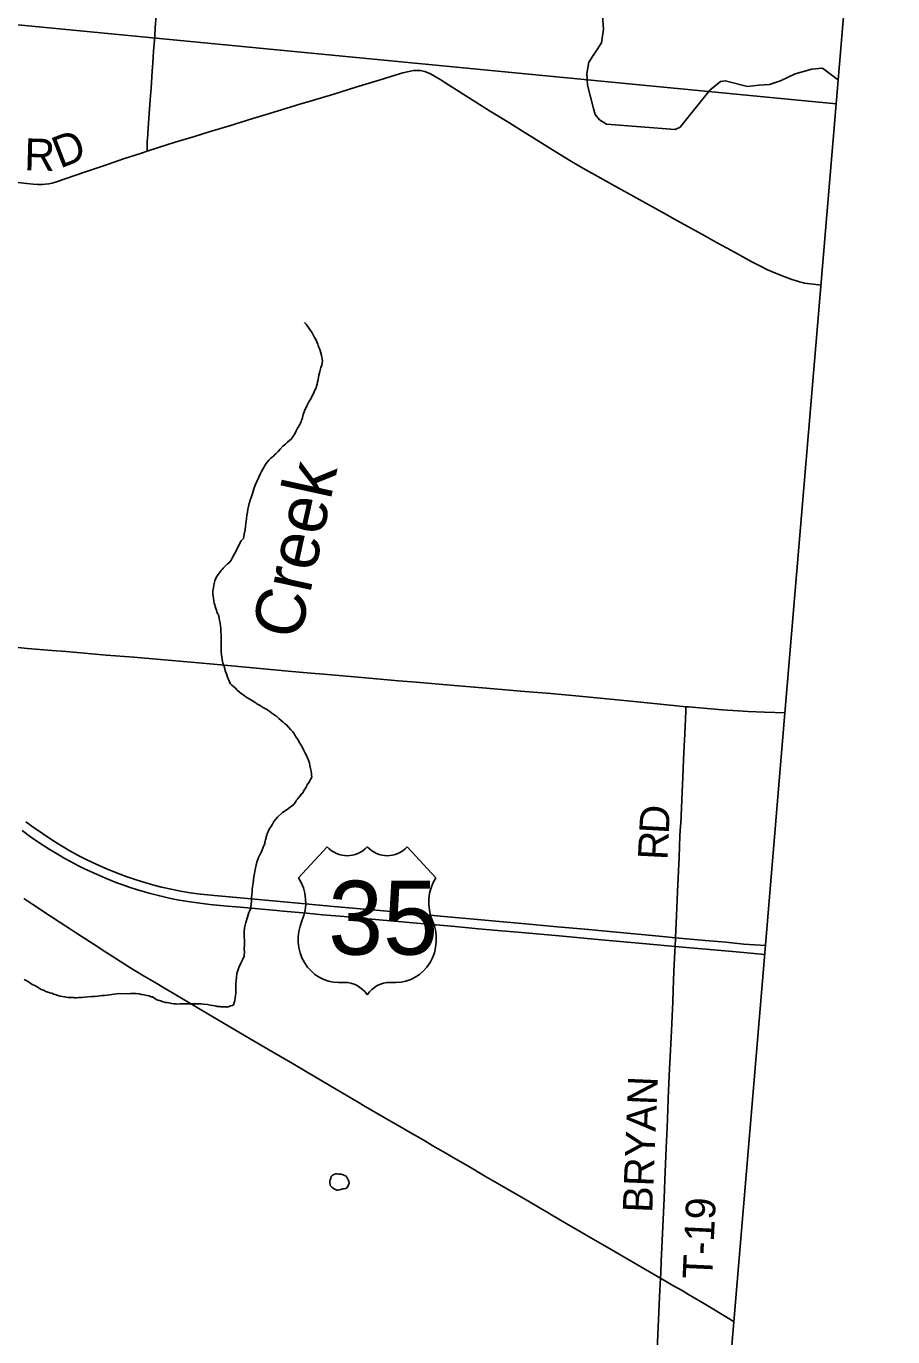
# Model space of a CAD drawing. Extents: x -13.9 to 69.1, y -25.2 to 26.1.
# Drawn here: x 6.483 to 7.963, y 16.353 to 18.591 of the extents above; entities that cross this region are included whole.
import ezdxf

# ---------------------------------------------------------------- set-up
doc = ezdxf.new("R2010")
doc.units = 0
for name, color, linetype in [('GM_X_County_Road', 7, 'Continuous'), ('GM_X_County_Road_Text', 7, 'Continuous'), ('GM_X_Minor_Lake', 7, 'Continuous'), ('GM_X_Minor_River', 7, 'Continuous'), ('GM_X_Minor_River_Text', 7, 'Continuous'), ('GM_X_State_Route', 7, 'Continuous'), ('GM_X_Township', 7, 'Continuous'), ('GM_X_Township_Road', 7, 'Continuous'), ('GM_X_Township_Road_Text', 7, 'Continuous'), ('GM_X_US_Location', 7, 'Continuous'), ('GM_X_US_Route', 7, 'Continuous'), ('GM_X_US_Shield', 7, 'Continuous')]:
    doc.layers.add(name, color=color, linetype=linetype)

msp = doc.modelspace()

# ---------------------------------------------------------------- linework, layer by layer
at = {"layer": 'GM_X_County_Road'}
for points in [[(6.6892, 18.378), (6.7087, 18.3844), (6.7375, 18.3932), (6.7705, 18.4032), (6.7954, 18.4109), (6.83, 18.4215), (6.8699, 18.4335), (6.8986, 18.4424), (6.9502, 18.4582), (6.9715, 18.4646), (7.0082, 18.4756), (7.046, 18.4871), (7.0854, 18.499), (7.113, 18.5076), (7.1258, 18.5115), (7.1339, 18.5136), (7.139, 18.5148), (7.1443, 18.5156), (7.1486, 18.5159), (7.1527, 18.5159), (7.1563, 18.5155), (7.1605, 18.5147), (7.1638, 18.5138), (7.1675, 18.5126), (7.1722, 18.5106), (7.1773, 18.508), (7.1831, 18.5045), (7.1908, 18.4997), (7.1979, 18.4952), (7.2509, 18.4618), (7.2742, 18.4471), (7.3068, 18.4269), (7.3302, 18.4123), (7.3499, 18.4002), (7.3772, 18.3832), (7.4011, 18.3682), (7.4141, 18.3604), (7.4335, 18.349), (7.4589, 18.3346), (7.4874, 18.3188), (7.5257, 18.2975), (7.5729, 18.2713), (7.5901, 18.2619), (7.6417, 18.2333), (7.6619, 18.2222), (7.6875, 18.2082), (7.7116, 18.1948), (7.7219, 18.1892), (7.7367, 18.1815), (7.7489, 18.1755), (7.7544, 18.1728), (7.7652, 18.1685), (7.7785, 18.1632), (7.7902, 18.1591), (7.7985, 18.1563), (7.8031, 18.155), (7.8078, 18.1539), (7.8119, 18.1528), (7.8169, 18.1518), (7.8408, 18.1492)], [(6.4236, 18.3298), (6.4841, 18.323), (6.4945, 18.3219), (6.5028, 18.3213), (6.5099, 18.3212), (6.5154, 18.3215), (6.5213, 18.3223), (6.5272, 18.3236), (6.5346, 18.3258), (6.5826, 18.3421), (6.6216, 18.3553), (6.649, 18.3647), (6.6797, 18.3748), (6.6892, 18.378)], [(6.4787, 17.1015), (6.4943, 17.0913), (6.5023, 17.0861), (6.5127, 17.0792), (6.5411, 17.0608), (6.5586, 17.0494), (6.569, 17.0426), (6.6054, 17.0189), (6.6125, 17.0143), (6.6295, 17.0032), (6.6538, 16.9877), (6.66, 16.9838), (6.6831, 16.9698), (6.7029, 16.958), (6.7189, 16.9485), (6.7325, 16.9405), (6.7989, 16.9013), (6.8308, 16.8823), (6.8555, 16.8678), (6.8954, 16.8445), (6.9386, 16.8192), (6.975, 16.7978), (7.0128, 16.7755), (7.0487, 16.7544), (7.0617, 16.7467), (7.105, 16.7214), (7.122, 16.7116), (7.1386, 16.702), (7.1605, 16.6894), (7.1712, 16.6832), (7.1775, 16.6795), (7.1994, 16.6667), (7.211, 16.6598), (7.2368, 16.6449), (7.2674, 16.627), (7.2913, 16.6132), (7.3019, 16.607), (7.3204, 16.5962), (7.3364, 16.5869), (7.3608, 16.5727), (7.3724, 16.5659), (7.3797, 16.5617), (7.4048, 16.5468), (7.4131, 16.542), (7.4307, 16.5319), (7.4472, 16.5223), (7.475, 16.5063), (7.561, 16.4562), (7.5658, 16.4534)], [(7.5658, 16.4534), (7.5786, 16.4461), (7.5873, 16.441), (7.6029, 16.432), (7.6141, 16.4255), (7.6412, 16.4095), (7.6523, 16.4029), (7.6742, 16.3895), (7.6919, 16.3788)]]:
    msp.add_lwpolyline(points, dxfattribs=at)
at = {"layer": 'GM_X_Minor_Lake'}
msp.add_lwpolyline([(7.0012, 16.6176), (7.0012, 16.6186), (7.0019, 16.6215), (7.0029, 16.6241), (7.0036, 16.627), (7.0054, 16.6288), (7.0081, 16.6306), (7.0108, 16.6313), (7.0135, 16.6316), (7.0162, 16.6312), (7.0192, 16.6312), (7.0209, 16.6311), (7.0226, 16.6304), (7.0243, 16.63), (7.0263, 16.6289), (7.0286, 16.6281), (7.0306, 16.6256), (7.0333, 16.6204), (7.0339, 16.6182), (7.0343, 16.6157), (7.0335, 16.6128), (7.0329, 16.611), (7.0318, 16.6092), (7.0305, 16.6074), (7.0284, 16.6067), (7.0257, 16.606), (7.0227, 16.6057), (7.0203, 16.605), (7.0176, 16.6043), (7.0156, 16.6039), (7.0132, 16.6039), (7.0112, 16.6047), (7.0095, 16.6054), (7.0048, 16.6088), (7.0021, 16.6114), (7.0012, 16.6176)], dxfattribs=at)
at = {"layer": 'GM_X_Minor_River'}
for points in [[(7.87, 18.4995), (7.8429, 18.5197), (7.8243, 18.5179), (7.7962, 18.5101), (7.771, 18.4979), (7.7521, 18.4921), (7.7342, 18.4906), (7.7146, 18.4884), (7.6766, 18.4983), (7.6682, 18.497), (7.6501, 18.4821), (7.5995, 18.4191), (7.591, 18.4149), (7.4738, 18.4241), (7.4621, 18.4313), (7.4545, 18.4405), (7.4517, 18.4511), (7.4412, 18.4909), (7.4402, 18.5106), (7.4435, 18.5298), (7.4653, 18.5628), (7.4684, 18.5864), (7.4671, 18.609)], [(6.8126, 17.6574), (6.814, 17.6596), (6.8157, 17.6618), (6.8174, 17.6636), (6.8194, 17.6657), (6.8215, 17.6679), (6.8239, 17.6704), (6.8266, 17.6733), (6.8293, 17.6751), (6.831, 17.6772), (6.8327, 17.6797), (6.8348, 17.683), (6.8424, 17.6978), (6.8458, 17.7054), (6.8499, 17.7126), (6.8537, 17.7166), (6.8551, 17.7238), (6.8565, 17.7315), (6.8573, 17.7373), (6.8577, 17.742), (6.8584, 17.7464), (6.8588, 17.7503), (6.8595, 17.7565), (6.8606, 17.7616), (6.8616, 17.7667), (6.8627, 17.7714), (6.8637, 17.7761), (6.8655, 17.7819), (6.8672, 17.7863), (6.8683, 17.7902), (6.8697, 17.795), (6.8714, 17.8011), (6.8738, 17.8076), (6.8766, 17.8141), (6.88, 17.8214), (6.8825, 17.8264), (6.8845, 17.8311), (6.8869, 17.8351), (6.889, 17.8387), (6.8914, 17.8427), (6.8945, 17.847), (6.8976, 17.8506), (6.9006, 17.8539), (6.9033, 17.856), (6.905, 17.8571), (6.9078, 17.8603), (6.9098, 17.8614), (6.9129, 17.8653), (6.9163, 17.8693), (6.9211, 17.874), (6.9258, 17.8776), (6.9292, 17.8808), (6.9361, 17.8869), (6.9371, 17.8887), (6.9388, 17.8912), (6.9402, 17.8934), (6.9419, 17.8966), (6.9436, 17.9003), (6.946, 17.905), (6.9484, 17.9086), (6.9501, 17.9111), (6.9512, 17.9133), (6.9522, 17.9162), (6.9532, 17.9187), (6.9539, 17.9205), (6.9546, 17.923), (6.956, 17.9285), (6.9588, 17.9357), (6.9623, 17.9433), (6.9657, 17.9498), (6.9688, 17.9552), (6.9709, 17.9592), (6.9729, 17.9632), (6.9746, 17.9668), (6.9764, 17.9711), (6.9778, 17.974), (6.9788, 17.9769), (6.9795, 17.9802), (6.9802, 17.9842), (6.9813, 17.9882), (6.982, 17.9914), (6.9827, 17.9954), (6.9841, 18.0016), (6.9859, 18.0085), (6.9879, 18.0128), (6.9887, 18.0201), (6.9871, 18.0292), (6.9848, 18.0376), (6.9832, 18.0424), (6.9822, 18.0442), (6.9815, 18.046), (6.9809, 18.0482), (6.9792, 18.0522), (6.9772, 18.0566), (6.9752, 18.0599), (6.9736, 18.0632), (6.9713, 18.068), (6.9609, 18.0826), (6.9589, 18.0848), (6.9579, 18.0852), (6.9579, 18.0852)], [(6.9631, 17.3417), (6.9614, 17.3461), (6.9595, 17.3501), (6.9571, 17.3542), (6.9555, 17.3582), (6.9535, 17.3615), (6.9522, 17.3637), (6.9512, 17.3655), (6.9498, 17.3677), (6.9485, 17.3703), (6.9465, 17.3732), (6.9432, 17.378), (6.9409, 17.3824), (6.9379, 17.3861), (6.9349, 17.3897), (6.9272, 17.3982), (6.9242, 17.4004), (6.9215, 17.403), (6.9181, 17.4056), (6.9145, 17.4089), (6.9108, 17.4126), (6.9058, 17.4159), (6.9024, 17.4185), (6.8991, 17.4211), (6.8957, 17.4233), (6.893, 17.4251), (6.8903, 17.4263), (6.8887, 17.4274), (6.887, 17.4281), (6.8843, 17.43), (6.8813, 17.4318), (6.8789, 17.4333), (6.8766, 17.4344), (6.8749, 17.4359), (6.8729, 17.437), (6.8709, 17.4381), (6.8685, 17.4396), (6.8662, 17.4411), (6.8635, 17.4426), (6.8608, 17.4445), (6.8581, 17.4463), (6.8551, 17.4485), (6.8514, 17.4504), (6.8491, 17.4522), (6.8464, 17.4548), (6.8434, 17.4574), (6.84, 17.4607), (6.8367, 17.4637), (6.834, 17.4659), (6.832, 17.4681), (6.8307, 17.4699), (6.83, 17.4717), (6.829, 17.4743), (6.8274, 17.478), (6.8261, 17.4812), (6.8248, 17.4856), (6.8228, 17.4907), (6.8215, 17.4962), (6.8202, 17.5002), (6.8189, 17.5035), (6.8182, 17.5068), (6.8176, 17.5101), (6.8169, 17.5134), (6.816, 17.5228), (6.8157, 17.5265), (6.8157, 17.5294), (6.8158, 17.5326), (6.8158, 17.5363), (6.8159, 17.541), (6.8159, 17.5468), (6.816, 17.5527), (6.8153, 17.5574), (6.815, 17.5625), (6.8144, 17.5679), (6.8138, 17.5749), (6.8125, 17.5796), (6.8116, 17.5843), (6.8102, 17.588), (6.8086, 17.5909), (6.8076, 17.5939), (6.8066, 17.5971), (6.8056, 17.6004), (6.8047, 17.6033), (6.804, 17.6063), (6.8034, 17.6095), (6.8027, 17.6146), (6.8021, 17.6183), (6.8018, 17.6216), (6.8018, 17.6245), (6.8018, 17.627), (6.8022, 17.6296), (6.8026, 17.6328), (6.8033, 17.6361), (6.8037, 17.6394), (6.8044, 17.6419), (6.8051, 17.6444), (6.8061, 17.6473), (6.8078, 17.651), (6.8095, 17.6535), (6.8109, 17.6553), (6.8126, 17.6574)], [(6.835, 16.9192), (6.8367, 16.9199), (6.8378, 16.9243), (6.8392, 16.9276), (6.8399, 16.9323), (6.8403, 16.9359), (6.8406, 16.9395), (6.8407, 16.9439), (6.8407, 16.9501), (6.8411, 16.9559), (6.8412, 16.9617), (6.8419, 16.9668), (6.8427, 16.9737), (6.8458, 16.9838), (6.8499, 16.9925), (6.853, 16.9979), (6.8541, 17.0008), (6.8551, 17.0026), (6.8551, 17.0048), (6.8555, 17.0095), (6.8552, 17.0157), (6.8556, 17.023), (6.8557, 17.0285), (6.8554, 17.0321), (6.8551, 17.035), (6.8551, 17.0401), (6.8552, 17.0452), (6.8559, 17.0517), (6.8577, 17.0608), (6.8605, 17.0699), (6.8629, 17.0778), (6.865, 17.0814), (6.8657, 17.0843), (6.8664, 17.0869), (6.8675, 17.0974), (6.8676, 17.1029), (6.8683, 17.108), (6.8687, 17.1127), (6.8687, 17.1167), (6.8694, 17.1218), (6.8702, 17.1283), (6.8709, 17.1337), (6.8716, 17.1385), (6.8727, 17.1446), (6.8741, 17.1515), (6.8752, 17.1562), (6.8766, 17.1635), (6.8797, 17.1718), (6.8828, 17.1787), (6.8849, 17.1816), (6.8873, 17.1892), (6.889, 17.1928), (6.8901, 17.1957), (6.8904, 17.1979), (6.8908, 17.1997), (6.8915, 17.2019), (6.8925, 17.2051), (6.8929, 17.2073), (6.8936, 17.2098), (6.8943, 17.212), (6.8953, 17.2149), (6.8964, 17.2174), (6.8978, 17.22), (6.8991, 17.2218), (6.9005, 17.2239), (6.9019, 17.2261), (6.9036, 17.2286), (6.906, 17.233), (6.9121, 17.2405), (6.9207, 17.2484), (6.9285, 17.2538), (6.9339, 17.2577), (6.9376, 17.2606), (6.9397, 17.262), (6.9435, 17.2674), (6.9445, 17.2696), (6.9459, 17.2714), (6.9472, 17.2736), (6.9493, 17.2754), (6.9506, 17.2772), (6.9524, 17.2797), (6.9544, 17.2815), (6.9558, 17.2833), (6.9571, 17.2862), (6.9595, 17.289), (6.9613, 17.293), (6.9623, 17.2952), (6.9643, 17.2981), (6.9654, 17.2999), (6.9671, 17.3024), (6.9685, 17.3049), (6.9695, 17.3067), (6.9705, 17.3096), (6.9702, 17.3115), (6.9702, 17.3147), (6.9696, 17.3191), (6.9686, 17.3235), (6.9673, 17.3286), (6.9664, 17.333), (6.9647, 17.3381), (6.9631, 17.3417)], [(6.4793, 16.9632), (6.484, 16.961), (6.4887, 16.958), (6.4931, 16.955), (6.4985, 16.9528), (6.5018, 16.9509), (6.5052, 16.9487), (6.5085, 16.9465), (6.5122, 16.945), (6.5163, 16.9431), (6.52, 16.942), (6.5233, 16.9409), (6.5267, 16.9401), (6.5294, 16.9386), (6.5324, 16.9378), (6.5368, 16.9363), (6.5408, 16.9352), (6.5449, 16.9344), (6.5483, 16.934), (6.5516, 16.9332), (6.5547, 16.9328), (6.5574, 16.9328), (6.5604, 16.9328), (6.5634, 16.9327), (6.5655, 16.9323), (6.5682, 16.9323), (6.5719, 16.9326), (6.578, 16.9329), (6.5827, 16.9332), (6.5881, 16.9339), (6.5942, 16.9345), (6.5999, 16.9345), (6.605, 16.9351), (6.609, 16.9354), (6.6128, 16.9358), (6.6165, 16.9361), (6.6212, 16.9368), (6.6259, 16.9374), (6.6324, 16.9384), (6.6371, 16.9387), (6.6418, 16.9394), (6.6553, 16.9392), (6.6607, 16.9395), (6.6658, 16.9395), (6.6708, 16.9394), (6.6759, 16.939), (6.6799, 16.9379), (6.6843, 16.9371), (6.6894, 16.9359), (6.6928, 16.9355), (6.6954, 16.9344), (6.6971, 16.934), (6.6988, 16.9336), (6.7008, 16.9321), (6.7035, 16.9303), (6.7062, 16.9288), (6.7122, 16.9269), (6.717, 16.9254), (6.7207, 16.9243), (6.7234, 16.9239), (6.7264, 16.9235), (6.7291, 16.9227), (6.7314, 16.9223), (6.7352, 16.9219), (6.7392, 16.9219), (6.7426, 16.9215), (6.7456, 16.9218), (6.749, 16.9217), (6.7537, 16.922), (6.7574, 16.9216), (6.7622, 16.9219), (6.7662, 16.9219), (6.7699, 16.9219), (6.7726, 16.9218), (6.775, 16.9218), (6.777, 16.9218), (6.7787, 16.9217), (6.7817, 16.9217), (6.7858, 16.9213), (6.7922, 16.9205), (6.7969, 16.9197), (6.8013, 16.9189), (6.805, 16.9185), (6.807, 16.9178), (6.8087, 16.9174), (6.8134, 16.917), (6.8151, 16.9169), (6.8175, 16.9169), (6.8205, 16.9169), (6.8242, 16.9168), (6.8259, 16.9164), (6.8276, 16.9168), (6.8293, 16.9171), (6.832, 16.9182), (6.835, 16.9192)]]:
    msp.add_lwpolyline(points, dxfattribs=at)
at = {"layer": 'GM_X_State_Route'}
msp.add_lwpolyline([(6.4575, 17.5313), (6.4851, 17.5289), (6.5264, 17.5255), (6.5512, 17.5235), (6.6195, 17.5174), (6.6664, 17.5136), (6.6989, 17.5108), (6.7772, 17.5044), (6.8025, 17.5018), (6.8824, 17.4946), (6.9237, 17.4906), (6.9556, 17.4875), (7.0041, 17.4835), (7.0625, 17.4785), (7.1187, 17.4735), (7.1485, 17.4711), (7.2074, 17.4661), (7.2619, 17.4616), (7.3341, 17.4555), (7.3788, 17.4519), (7.4278, 17.4473), (7.5153, 17.4386), (7.588, 17.4312), (7.6093, 17.4293), (7.6138, 17.4289), (7.6712, 17.424), (7.6987, 17.422), (7.7158, 17.4211), (7.7434, 17.42), (7.7794, 17.4187)], dxfattribs=at)
at = {"layer": 'GM_X_Township'}
msp.add_lwpolyline([(8.0976, 21.2145), (2.668, 21.2145), (2.5713, 21.1249), (2.5376, 21.0933), (2.5207, 21.0774), (2.9282, 20.5283), (2.3149, 19.9943), (2.3345, 19.9924), (2.4186, 19.989), (2.4692, 19.987), (2.5176, 19.987), (2.5995, 20.0118), (2.5714, 18.9023), (4.5288, 18.7816), (7.8661, 18.459), (7.9988, 20.0382), (8.0428, 20.5625)], close=True, dxfattribs=at)
msp.add_lwpolyline([(7.5668, 14.8972), (7.5796, 15.0495), (7.6196, 15.5251), (7.6913, 16.3786), (7.7402, 16.961), (7.7786, 17.4181), (7.8394, 18.1408), (7.8661, 18.459), (4.5288, 18.7816)], dxfattribs=at)
at = {"layer": 'GM_X_Township_Road'}
for points in [[(6.7023, 18.5755), (6.7032, 18.5885), (6.7051, 18.617)], [(6.698, 18.5144), (6.699, 18.5286), (6.7004, 18.5488), (6.7018, 18.5678), (6.7023, 18.5755)], [(6.6892, 18.378), (6.6892, 18.3811), (6.6893, 18.386), (6.6895, 18.3914), (6.6897, 18.3956), (6.6898, 18.3988), (6.6917, 18.426), (6.6946, 18.4664), (6.696, 18.4853), (6.698, 18.5144)], [(7.6003, 17.2257), (7.6005, 17.2299), (7.6019, 17.2566), (7.6047, 17.3231), (7.6053, 17.3386), (7.6065, 17.3617), (7.6075, 17.3831), (7.6087, 17.4086), (7.6091, 17.4217), (7.6093, 17.4293)], [(7.5793, 16.7603), (7.5809, 16.7994), (7.5827, 16.8321), (7.5842, 16.8641), (7.5868, 16.9247), (7.5876, 16.9455), (7.5889, 16.9769), (7.5906, 17.012), (7.591, 17.02), (7.5916, 17.0348), (7.5933, 17.0726), (7.5951, 17.1135), (7.5977, 17.1723), (7.5993, 17.2085), (7.6003, 17.2257)], [(7.5658, 16.4534), (7.5663, 16.4621), (7.5673, 16.4816), (7.5696, 16.5298), (7.5721, 16.5892), (7.5734, 16.6206), (7.5758, 16.6759), (7.5772, 16.7103), (7.5792, 16.7579), (7.5793, 16.7603)], [(7.5599, 16.3205), (7.5615, 16.3568), (7.5644, 16.4215), (7.5658, 16.4534)]]:
    msp.add_lwpolyline(points, dxfattribs=at)
at = {"layer": 'GM_X_US_Route'}
for points in [[(6.476, 17.2177), (6.4901, 17.2073), (6.5012, 17.1995), (6.522, 17.186), (6.5374, 17.1767), (6.5476, 17.1708), (6.5584, 17.1647), (6.5708, 17.1582), (6.5823, 17.1525), (6.598, 17.1453), (6.6185, 17.1363), (6.6376, 17.1285), (6.6459, 17.1254), (6.6606, 17.1203), (6.6712, 17.1169), (6.6808, 17.1142), (6.6931, 17.1107), (6.7108, 17.1061), (6.727, 17.1024), (6.7406, 17.0997), (6.7591, 17.0965), (6.7755, 17.0941), (6.7964, 17.0915), (6.8261, 17.0888), (6.8412, 17.0876)], [(6.4821, 17.2329), (6.4964, 17.2225), (6.5107, 17.2125), (6.5281, 17.2008), (6.543, 17.1916), (6.5576, 17.1831), (6.5739, 17.1742), (6.5854, 17.1684), (6.6026, 17.1601), (6.619, 17.1529), (6.6371, 17.1456), (6.6538, 17.1393), (6.6707, 17.1336), (6.6872, 17.1284), (6.7033, 17.1239), (6.7141, 17.1212), (6.7303, 17.1175), (6.7466, 17.1142), (6.7631, 17.1115), (6.7806, 17.1093), (6.8104, 17.1062), (6.8605, 17.1015), (6.9475, 17.0935), (7.0076, 17.0882), (7.1128, 17.0788), (7.1905, 17.0717), (7.3419, 17.058), (7.3893, 17.0536), (7.4367, 17.0493), (7.5638, 17.0373), (7.5916, 17.0348), (7.6425, 17.0302), (7.6777, 17.0272), (7.7083, 17.024), (7.7457, 17.0215)], [(6.8412, 17.0876), (6.8553, 17.0864), (6.9109, 17.0811), (6.9214, 17.08), (6.9621, 17.0764), (6.9891, 17.074), (7.026, 17.0707), (7.0475, 17.0687), (7.0855, 17.0652), (7.1693, 17.0579), (7.2155, 17.0538), (7.2552, 17.0501), (7.2811, 17.0477), (7.3289, 17.0434), (7.3928, 17.0377), (7.4589, 17.0319), (7.5416, 17.0243), (7.591, 17.02), (7.6104, 17.0183), (7.6826, 17.0116), (7.7445, 17.0061)]]:
    msp.add_lwpolyline(points, dxfattribs=at)
at = {"layer": 'GM_X_US_Shield'}
for p, q in [((6.9968, 17.1898), (6.9479, 17.1372)), ((7.1825, 17.1372), (7.1336, 17.1898)), ((7.0164, 16.9585), (7.0261, 16.9585)), ((7.1043, 16.9585), (7.1141, 16.9585))]:
    msp.add_line(p, q, dxfattribs=at)
for centre, major_axis, start_param, end_param in [((7.031, 17.2274), (0, -0.0526), 5.507788, 7.058583), ((7.0994, 17.2274), (0, -0.0526), 5.507788, 7.058583), ((6.8919, 17.095), (0, 0.0736), 4.268152, 5.32327), ((7.2386, 17.095), (0, -0.0736), 4.101508, 5.156625), ((7.0156, 17.0321), (0, -0.0736), 4.273123, 6.294325), ((7.1149, 17.0321), (0, -0.0736), 6.272046, 8.293248), ((7.0261, 16.9059), (0, 0.0526), 5.35589, 6.283185), ((7.1043, 16.9059), (0, 0.0526), 0, 0.927295)]:
    msp.add_ellipse(centre, major_axis=major_axis, ratio=0.929448, start_param=start_param, end_param=end_param, dxfattribs=at)

# ---------------------------------------------------------------- texts
at = {"layer": 'GM_X_County_Road_Text'}
for s, height, rotation, p in [('R', 0.0544, 358.4156, (6.479, 18.3456)), ('D', 0.054, 21.1524, (6.5406, 18.348))]:
    msp.add_text(s, height=height, rotation=rotation, dxfattribs=at).set_placement(p)
at = {"layer": 'GM_X_Minor_River_Text'}
msp.add_text('Creek', height=0.08458, rotation=77.6398, dxfattribs=at).set_placement((6.95, 17.5413))
at = {"layer": 'GM_X_Township_Road_Text'}
for s, height, rotation, p in [('D', 0.0506, 86.8252, (7.58, 17.2113)), ('R', 0.0506, 87.1979, (7.5778, 17.1668)), ('BRYAN', 0.05055, 87.6532, (7.5519, 16.5644)), ('T-19', 0.05056, 87.3662, (7.6541, 16.4511))]:
    msp.add_text(s, height=height, rotation=rotation, dxfattribs=at).set_placement(p)
at = {"layer": 'GM_X_US_Location'}
for s in ['0', '/']:
    msp.add_text(s, height=0.000181, dxfattribs=at).set_placement((7.0652, 17.0679))
msp.add_text('35', height=0.000181, rotation=0, dxfattribs=at).set_placement((7.0304, 17.0304))
at = {"layer": 'GM_X_US_Shield'}
msp.add_text('35', height=0.12619, dxfattribs=at).set_placement((6.9985, 17.0058))

doc.saveas('drawing.dxf')
